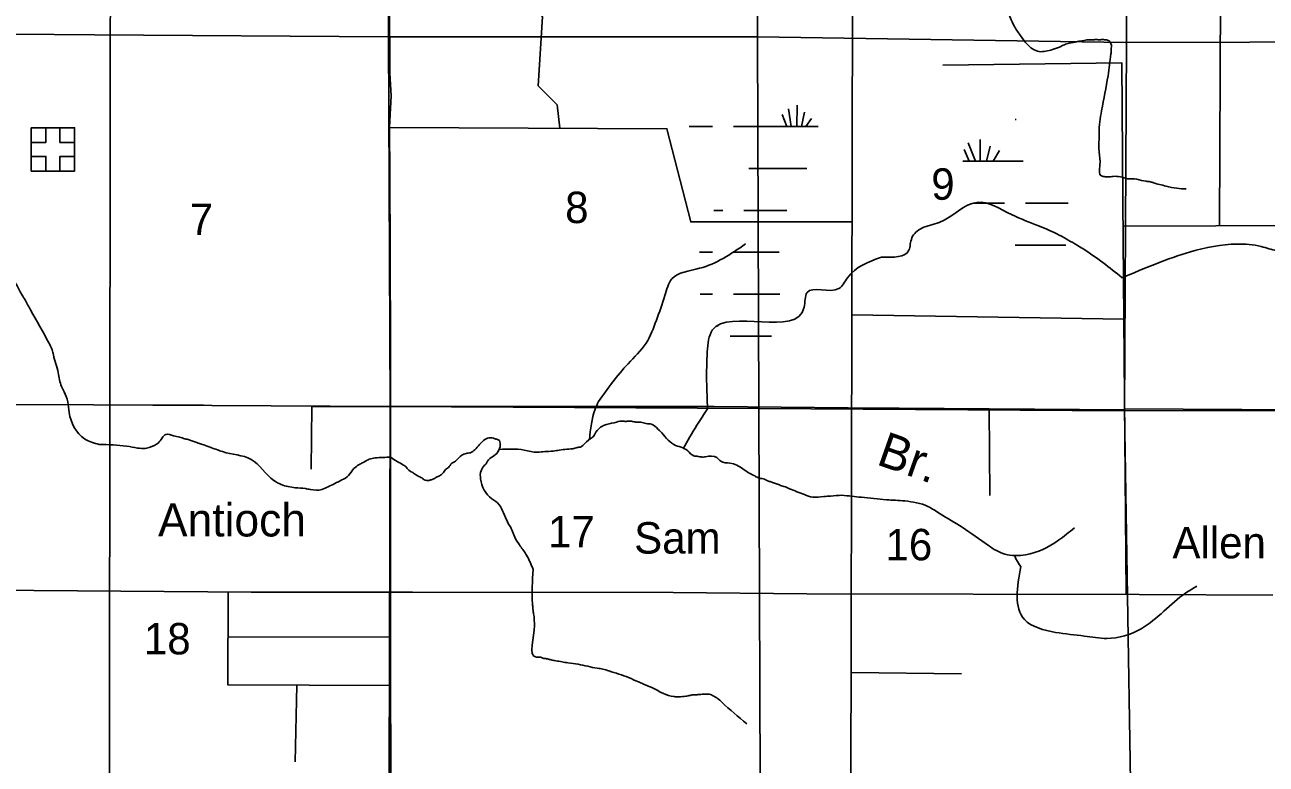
# Model space of a CAD drawing. Extents: x 380424 to 701066, y 1117407 to 1412949.
# Drawn here: x 574618 to 592389, y 1347425 to 1358008 of the extents above; entities that cross this region are included whole.
import ezdxf

# ---------------------------------------------------------------- set-up
doc = ezdxf.new("R2010")
doc.units = 0
for name, color, linetype in [('Communities and Subdivisions Names without Post Office', 7, 'Continuous'), ('County Roads Related Text', 7, 'Continuous'), ('County Routes Highway Center Lines', 7, 'Continuous'), ('Culture', 7, 'Continuous'), ('Local Roads Paved', 7, 'Continuous'), ('Narrow River Creek and Branch and Slough', 7, 'Continuous'), ('Narrow River Creek and Branch and Slough Text', 7, 'Continuous'), ('Section Lines', 7, 'Continuous'), ('Section Numbers', 7, 'Continuous'), ('Swamps', 7, 'Continuous')]:
    doc.layers.add(name, color=color, linetype=linetype)

msp = doc.modelspace()

# ---------------------------------------------------------------- linework, layer by layer
at = {"layer": 'County Routes Highway Center Lines'}
msp.add_lwpolyline([(572255, 1349932), (577859, 1349889), (580167, 1349889), (583901, 1349880), (585815, 1349862), (590572, 1349854), (592486, 1349845)], dxfattribs=at)
at = {"layer": 'Culture'}
for points in [[(574709, 1356534), (575329, 1356534), (575329, 1355914), (574709, 1355914)], [(574919, 1356534), (575119, 1356534), (575119, 1356324), (575329, 1356324), (575329, 1356124), (575119, 1356124), (575119, 1355914), (574919, 1355914), (574919, 1356124), (574709, 1356124), (574709, 1356324), (574919, 1356324)]]:
    msp.add_lwpolyline(points, close=True, dxfattribs=at)
at = {"layer": 'Local Roads Paved'}
for p, q in [((586429, 1341036), (586471, 1360503)), ((591723, 1355130), (591745, 1360466)), ((590352, 1353794), (586457, 1353855)), ((575836, 1352568), (577177, 1352566)), ((588432, 1351269), (588424, 1352511)), ((577527, 1349242), (579854, 1349248)), ((586446, 1348739), (588028, 1348719)), ((578514, 1348555), (578490, 1347460))]:
    msp.add_line(p, q, dxfattribs=at)
for points in [[(575856, 1371618), (575827, 1344606), (577212, 1344576), (577225, 1341630), (577228, 1340951), (577288, 1324760), (578560, 1324774), (578525, 1320990)], [(579787, 1363133), (579806, 1362464), (579832, 1360472), (579832, 1358822), (579841, 1357516), (579841, 1357318), (579864, 1356990), (579838, 1356543), (579845, 1355858), (579848, 1354747), (579851, 1353383), (579851, 1352557), (579854, 1349891), (579854, 1348546), (579857, 1347469), (579864, 1346025), (579877, 1343343), (579873, 1342707), (578135, 1342493), (569164, 1342370), (568217, 1342370), (568201, 1340658), (558506, 1340671)], [(581459, 1360492), (581547, 1358943), (582030, 1358123), (581967, 1357135), (582240, 1356862), (582278, 1356527)], [(590384, 1349854), (590339, 1355492), (590323, 1357462), (587761, 1357432)], [(586460, 1355187), (584152, 1355187), (583811, 1356521), (579838, 1356537)], [(601084, 1353834), (601071, 1355150), (599625, 1355159), (590342, 1355125)], [(590363, 1352497), (587133, 1352521), (586406, 1352526), (584487, 1352544), (578724, 1352544), (578719, 1351646)], [(599756, 1352497), (598023, 1352497), (595808, 1352487), (592040, 1352502), (590363, 1352511)], [(579854, 1348551), (577524, 1348558), (577530, 1349891)]]:
    msp.add_lwpolyline(points, dxfattribs=at)
at = {"layer": 'Narrow River Creek and Branch and Slough'}
for points in [[(586420, 1358661), (586662, 1358696), (586871, 1358715), (587027, 1358724), (587167, 1358744), (587263, 1358754), (587564, 1358775), (587611, 1358786), (587685, 1358791), (587743, 1358786), (587875, 1358775), (587975, 1358749), (588034, 1358723), (588134, 1358691), (588371, 1358521), (588458, 1358424), (588502, 1358394), (588545, 1358360), (588608, 1358312), (588696, 1358181), (588788, 1357977), (588880, 1357841), (588962, 1357734), (589139, 1357626), (589328, 1357654), (589388, 1357672), (589447, 1357697), (589518, 1357731), (589593, 1357751), (589655, 1357762), (589690, 1357769), (589714, 1357773), (589737, 1357775), (589750, 1357778), (589762, 1357780), (589841, 1357793), (589880, 1357793), (589901, 1357794), (589919, 1357794), (589934, 1357796), (590002, 1357794), (590031, 1357796), (590091, 1357794), (590109, 1357792), (590118, 1357789), (590139, 1357778), (590174, 1357692), (590169, 1357658), (590169, 1357628), (590166, 1357591)], [(590166, 1357591), (590125, 1357279), (590033, 1356779), (589996, 1356460), (589996, 1356357), (589993, 1356276), (590000, 1356184), (590008, 1356000), (590030, 1355845), (590085, 1355834), (590114, 1355834), (590162, 1355834), (590199, 1355838), (590405, 1355805)], [(590405, 1355805), (590537, 1355797), (590673, 1355768), (590728, 1355761), (590776, 1355746), (590861, 1355724), (590956, 1355698), (591111, 1355669), (591243, 1355658)], [(586881, 1354683), (587273, 1354780), (587317, 1354959), (587459, 1355097), (587709, 1355180), (588250, 1355467), (588743, 1355292), (589142, 1355127), (589426, 1354998), (589683, 1354852), (589762, 1354804), (590329, 1354387)], [(582830, 1352614), (583253, 1353156), (583512, 1353452), (583659, 1353779), (583781, 1354132), (583881, 1354370), (584277, 1354523), (584614, 1354665), (584936, 1354871)], [(590329, 1354387), (591306, 1354759), (591973, 1354870), (592316, 1354835), (592542, 1354774), (592863, 1354744), (593135, 1354688), (593573, 1354586), (593877, 1354515), (594242, 1354368), (594524, 1354456), (594740, 1354513), (594813, 1354529), (595100, 1354598)], [(584392, 1352511), (584388, 1353329), (584460, 1353637), (585776, 1353965), (585816, 1354175), (586270, 1354232), (586396, 1354388), (586881, 1354683)], [(574458, 1354354), (574493, 1354298), (574550, 1354188), (574588, 1354122), (574637, 1354044), (574657, 1354004), (574700, 1353926), (574962, 1353454), (575008, 1353356), (575027, 1353283), (575096, 1353029), (575143, 1352829), (575180, 1352755), (575233, 1352613), (575252, 1352459), (575474, 1352081), (575683, 1352002)], [(582701, 1352073), (582783, 1352507), (582830, 1352614)], [(584043, 1351938), (584238, 1352276), (584392, 1352511)], [(581410, 1351929), (581765, 1351921), (581955, 1351890), (582060, 1351900), (582182, 1351906), (582272, 1351921), (582377, 1351932), (582493, 1351948), (582525, 1351958), (582572, 1351964), (582604, 1351985), (582715, 1352085), (582752, 1352111), (582794, 1352175), (582889, 1352264), (582947, 1352286), (583089, 1352321), (583182, 1352336), (583213, 1352331), (583264, 1352336), (583337, 1352326), (583394, 1352321), (583435, 1352321), (583512, 1352300), (583591, 1352291), (583680, 1352222), (583712, 1352191), (583910, 1352000), (584108, 1351911), (584193, 1351838), (584258, 1351830), (584298, 1351822), (584363, 1351826), (584525, 1351814), (584582, 1351761), (584711, 1351733), (584898, 1351652), (584979, 1351595), (585068, 1351550), (585112, 1351526), (585157, 1351514), (585169, 1351514), (585205, 1351502), (585262, 1351477), (585310, 1351461), (585363, 1351441), (585420, 1351421), (585485, 1351401), (585565, 1351368), (585780, 1351283), (585897, 1351247), (586055, 1351255), (586156, 1351263), (586314, 1351275)], [(575683, 1352002), (576075, 1351976), (576231, 1351950), (576342, 1351944), (576414, 1351963), (576525, 1352022), (576584, 1352094), (576636, 1352146), (576747, 1352126), (576832, 1352107), (576910, 1352081), (576969, 1352068), (577021, 1352048), (577080, 1352028), (577119, 1352015), (577178, 1351996), (577282, 1351957), (577374, 1351924), (577446, 1351898), (577857, 1351787), (578183, 1351486), (578288, 1351428), (578490, 1351382), (578634, 1351369), (578705, 1351356), (578869, 1351356), (578960, 1351395), (579057, 1351442), (579155, 1351493), (579252, 1351555), (579330, 1351657), (579401, 1351711), (579451, 1351739), (579487, 1351758), (579549, 1351790), (579635, 1351809), (579857, 1351817)], [(579857, 1351817), (580041, 1351704), (580076, 1351680), (580099, 1351649), (580170, 1351598), (580224, 1351563), (580271, 1351536), (580299, 1351524), (580349, 1351489), (580392, 1351485), (580439, 1351497), (580482, 1351516), (580521, 1351536), (580552, 1351551), (580611, 1351598), (580654, 1351653), (580681, 1351672), (580732, 1351731), (580767, 1351751), (580825, 1351805), (580935, 1351872), (580997, 1351883), (581060, 1351926), (581204, 1352071), (581286, 1352098), (581325, 1352090), (581349, 1352082), (581396, 1352069), (581390, 1351895), (581243, 1351763), (581222, 1351726), (581200, 1351704), (581149, 1351626), (581142, 1351508), (581303, 1351225), (581361, 1351186), (581499, 1350957), (581548, 1350857), (581581, 1350800), (581617, 1350709), (581688, 1350580), (581780, 1350448), (581800, 1350417), (581894, 1350211)], [(586314, 1351275), (586594, 1351245), (586952, 1351210), (587214, 1351192), (587546, 1351113), (587721, 1351008), (588036, 1350816), (588412, 1350554), (588648, 1350431), (588945, 1350422), (589416, 1350629), (589643, 1350808)], [(588788, 1350404), (588814, 1350352), (588875, 1350256)], [(581894, 1350211), (581886, 1349721), (581892, 1349648), (581897, 1349605), (581902, 1349577), (581907, 1349537), (581910, 1349494), (581915, 1349410), (581945, 1348956), (582016, 1348951), (582049, 1348938), (582100, 1348933), (582125, 1348925), (582151, 1348918), (582219, 1348905), (582308, 1348890), (582392, 1348874), (582539, 1348854), (582813, 1348798), (582892, 1348786), (582980, 1348760), (583262, 1348664), (583402, 1348603), (583465, 1348577), (583602, 1348516), (583912, 1348392), (583980, 1348390), (584082, 1348397), (584142, 1348410), (584201, 1348418), (584259, 1348420), (584330, 1348425), (584333, 1348425), (584378, 1348428), (584449, 1348415), (584495, 1348390), (584533, 1348367), (584597, 1348311), (584954, 1348004)], [(588875, 1350256), (588928, 1349495), (589374, 1349311), (589785, 1349259), (590108, 1349224), (590598, 1349364), (591236, 1349874), (591394, 1349972)]]:
    msp.add_spline(points, degree=3, dxfattribs=at)
at = {"layer": 'Section Lines'}
for points in [[(579790, 1363121), (579826, 1357837), (579821, 1357838), (575614, 1357867), (574460, 1357872), (574493, 1363145), (575625, 1363139)], [(585074, 1363118), (585109, 1357836), (579826, 1357837), (579790, 1363121)], [(590380, 1363094), (590389, 1357757), (590374, 1357753), (585109, 1357836), (585074, 1363118), (585081, 1363118)], [(595679, 1363101), (595688, 1357771), (590389, 1357757), (590380, 1363094), (590393, 1363094)], [(579826, 1357837), (579848, 1352545), (579838, 1352545), (575603, 1352570), (574444, 1352573), (574460, 1357872), (575614, 1357867), (579821, 1357838)], [(585109, 1357836), (585126, 1352524), (585126, 1352514), (579848, 1352545), (579826, 1357837)], [(590389, 1357757), (590362, 1352483), (585126, 1352514), (585126, 1352524), (585109, 1357836), (590374, 1357753)], [(595688, 1357771), (595778, 1352491), (595779, 1352485), (590362, 1352483), (590389, 1357757)], [(579848, 1352545), (579835, 1347220), (575594, 1347253), (574462, 1347269), (574444, 1352573), (575603, 1352570), (579838, 1352545)], [(585126, 1352514), (585146, 1347197), (579864, 1347220), (579835, 1347220), (579848, 1352545)], [(590362, 1352483), (590447, 1347177), (585146, 1347197), (585126, 1352514)], [(595779, 1352485), (595822, 1347170), (595807, 1347170), (590447, 1347177), (590362, 1352483)]]:
    msp.add_lwpolyline(points, close=True, dxfattribs=at)
at = {"layer": 'Swamps'}
for p, q in [((585668, 1356552), (585673, 1356856)), ((585527, 1356553), (585461, 1356726)), ((585590, 1356552), (585550, 1356805)), ((585735, 1356552), (585778, 1356758)), ((585797, 1356552), (585881, 1356665)), ((584762, 1356552), (585362, 1356552)), ((588124, 1356318), (588227, 1356055)), ((588293, 1356366), (588293, 1356055)), ((588064, 1356221), (588135, 1356055)), ((588438, 1356270), (588385, 1356055)), ((588571, 1356209), (588482, 1356056)), ((585362, 1355952), (585812, 1355952)), ((588945, 1355455), (589395, 1355455)), ((584912, 1355352), (585362, 1355352)), ((584762, 1354752), (585362, 1354752)), ((588795, 1354856), (589395, 1354856)), ((584762, 1354152), (585362, 1354152))]:
    msp.add_line(p, q, dxfattribs=at)
for points in [[(584128, 1356552), (584462, 1356552)], [(585362, 1356552), (585977, 1356552)], [(588795, 1356655), (588811, 1356655)], [(588045, 1356055), (588912, 1356055)], [(584982, 1355952), (585362, 1355952)], [(588194, 1355455), (588645, 1355455)], [(589395, 1355455), (589554, 1355455)], [(584483, 1355352), (584612, 1355352)], [(585362, 1355352), (585528, 1355352)], [(584274, 1354752), (584462, 1354752)], [(585362, 1354752), (585419, 1354752)], [(589395, 1354856), (589522, 1354856)], [(584284, 1354152), (584462, 1354152)], [(585362, 1354152), (585424, 1354152)], [(584538, 1353706), (584528, 1353689)], [(584714, 1353552), (585308, 1353552)]]:
    msp.add_lwpolyline(points, dxfattribs=at)

# ---------------------------------------------------------------- texts
at = {"layer": 'Communities and Subdivisions Names without Post Office'}
msp.add_text('Antioch', height=475, rotation=0.0006, dxfattribs=at).set_placement((576524, 1350684))
at = {"layer": 'County Roads Related Text'}
for s, p in [('Sam', (583341, 1350439)), ('Allen', (591047, 1350371))]:
    msp.add_text(s, height=450, rotation=0.0006, dxfattribs=at).set_placement(p)
at = {"layer": 'Narrow River Creek and Branch and Slough Text'}
msp.add_text('Br.', height=500, rotation=340.5919, dxfattribs=at).set_placement((586793, 1351721))
at = {"layer": 'Section Numbers'}
for s, p in [('9', (587594, 1355504)), ('8', (582353, 1355170)), ('7', (576978, 1355000)), ('17', (582107, 1350528)), ('16', (586939, 1350343)), ('18', (576322, 1348996))]:
    msp.add_text(s, height=450, dxfattribs=at).set_placement(p)

doc.saveas('drawing.dxf')
